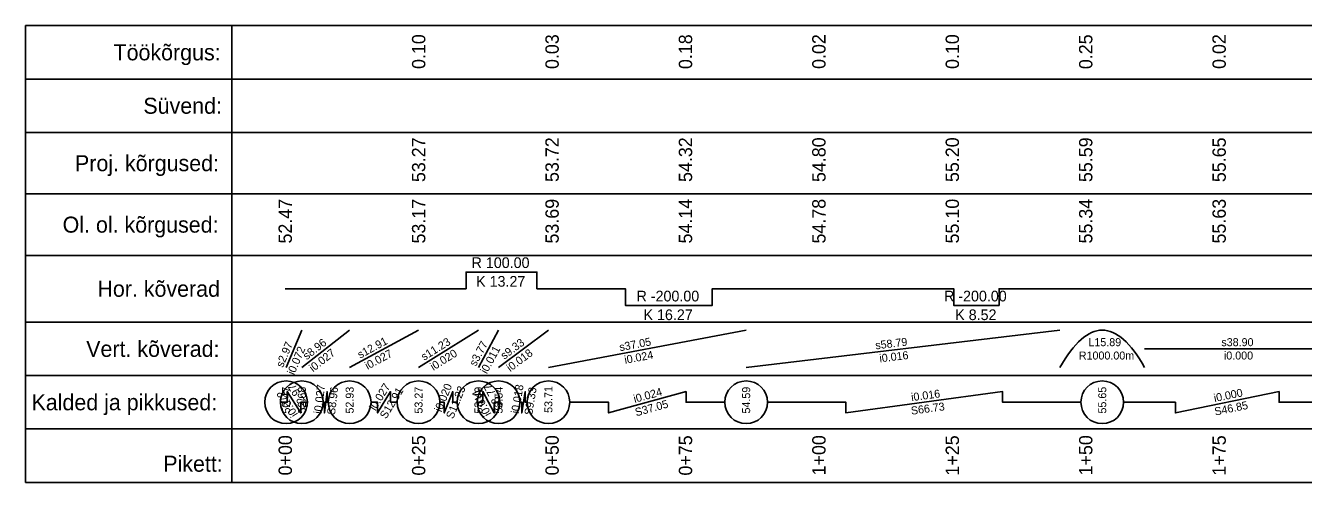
# Model space of a CAD drawing. Extents: x 655100 to 703495, y 6445581 to 6476602.
# Drawn here: x 669260.6 to 669500.1, y 6465749.1 to 6465834.6 of the extents above; entities that cross this region are included whole.
import ezdxf

# ---------------------------------------------------------------- set-up
doc = ezdxf.new("R2010")
doc.units = 0
for name, color, linetype in [('54', 7, 'Continuous'), ('Profile Annotation', 7, 'Continuous'), ('Prop_Benching', 7, 'Continuous')]:
    doc.layers.add(name, color=color, linetype=linetype)

msp = doc.modelspace()

# ---------------------------------------------------------------- linework, layer by layer
at = {"layer": '54'}
for points in [[(669299.3, 6465834.57), (669260.64, 6465834.57), (669260.64, 6465824.57), (669299.3, 6465824.57)], [(669309.3, 6465834.57), (669309.3, 6465834.57)], [(669334.3, 6465834.57), (669334.3, 6465834.57)], [(669359.3, 6465834.57), (669359.3, 6465834.57)], [(669384.3, 6465834.57), (669384.3, 6465834.57)], [(669409.3, 6465834.57), (669409.3, 6465834.57)], [(669434.3, 6465834.57), (669434.3, 6465834.57)], [(669459.3, 6465834.57), (669459.3, 6465834.57)], [(669484.3, 6465834.57), (669484.3, 6465834.57)], [(669299.3, 6465824.57), (669260.64, 6465824.57), (669260.64, 6465814.57), (669299.3, 6465814.57)], [(669309.3, 6465824.57), (669309.3, 6465824.57)], [(669334.3, 6465824.57), (669334.3, 6465824.57)], [(669359.3, 6465824.57), (669359.3, 6465824.57)], [(669384.3, 6465824.57), (669384.3, 6465824.57)], [(669409.3, 6465824.57), (669409.3, 6465824.57)], [(669434.3, 6465824.57), (669434.3, 6465824.57)], [(669459.3, 6465824.57), (669459.3, 6465824.57)], [(669484.3, 6465824.57), (669484.3, 6465824.57)], [(669299.3, 6465814.57), (669260.64, 6465814.57), (669260.64, 6465803.07), (669299.3, 6465803.07)], [(669309.3, 6465814.57), (669309.3, 6465814.57)], [(669334.3, 6465814.57), (669334.3, 6465814.57)], [(669359.3, 6465814.57), (669359.3, 6465814.57)], [(669384.3, 6465814.57), (669384.3, 6465814.57)], [(669409.3, 6465814.57), (669409.3, 6465814.57)], [(669434.3, 6465814.57), (669434.3, 6465814.57)], [(669459.3, 6465814.57), (669459.3, 6465814.57)], [(669484.3, 6465814.57), (669484.3, 6465814.57)], [(669299.3, 6465803.07), (669260.64, 6465803.07), (669260.64, 6465791.57), (669299.3, 6465791.57)], [(669309.3, 6465803.07), (669309.3, 6465803.07)], [(669334.3, 6465803.07), (669334.3, 6465803.07)], [(669359.3, 6465803.07), (669359.3, 6465803.07)], [(669384.3, 6465803.07), (669384.3, 6465803.07)], [(669409.3, 6465803.07), (669409.3, 6465803.07)], [(669434.3, 6465803.07), (669434.3, 6465803.07)], [(669459.3, 6465803.07), (669459.3, 6465803.07)], [(669484.3, 6465803.07), (669484.3, 6465803.07)], [(669299.3, 6465791.57), (669260.64, 6465791.57), (669260.64, 6465779.07), (669299.3, 6465779.07)], [(669309.3, 6465791.57), (669309.3, 6465791.57)], [(669343.19, 6465791.57), (669343.19, 6465791.57)], [(669356.46, 6465791.57), (669356.46, 6465791.57)], [(669373.06, 6465791.57), (669373.06, 6465791.57)], [(669389.33, 6465791.57), (669389.33, 6465791.57)], [(669434.56, 6465791.57), (669434.56, 6465791.57)], [(669443.08, 6465791.57), (669443.08, 6465791.57)], [(669299.3, 6465779.07), (669260.64, 6465779.07), (669260.64, 6465769.07), (669299.3, 6465769.07)], [(669309.45, 6465779.07), (669309.45, 6465779.07)], [(669312.41, 6465779.07), (669312.41, 6465779.07)], [(669321.37, 6465779.07), (669321.37, 6465779.07)], [(669334.28, 6465779.07), (669334.28, 6465779.07)], [(669345.51, 6465779.07), (669345.51, 6465779.07)], [(669349.28, 6465779.07), (669349.28, 6465779.07)], [(669358.61, 6465779.07), (669358.61, 6465779.07)], [(669395.67, 6465779.07), (669395.67, 6465779.07)], [(669454.46, 6465779.07), (669454.46, 6465779.07)], [(669470.34, 6465779.07), (669470.34, 6465779.07)], [(669299.3, 6465769.07), (669260.64, 6465769.07), (669260.64, 6465759.07), (669299.3, 6465759.07)], [(669309.45, 6465769.07), (669309.45, 6465769.07)], [(669312.41, 6465769.07), (669312.41, 6465769.07)], [(669321.37, 6465769.07), (669321.37, 6465769.07)], [(669334.28, 6465769.07), (669334.28, 6465769.07)], [(669345.51, 6465769.07), (669345.51, 6465769.07)], [(669349.28, 6465769.07), (669349.28, 6465769.07)], [(669358.61, 6465769.07), (669358.61, 6465769.07)], [(669395.67, 6465769.07), (669395.67, 6465769.07)], [(669454.46, 6465769.07), (669454.46, 6465769.07)], [(669470.34, 6465769.07), (669470.34, 6465769.07)], [(669299.3, 6465759.07), (669260.64, 6465759.07), (669260.64, 6465749.07), (669299.3, 6465749.07)], [(669309.3, 6465759.07), (669309.3, 6465759.07)], [(669334.3, 6465759.07), (669334.3, 6465759.07)], [(669359.3, 6465759.07), (669359.3, 6465759.07)], [(669384.3, 6465759.07), (669384.3, 6465759.07)], [(669409.3, 6465759.07), (669409.3, 6465759.07)], [(669434.3, 6465759.07), (669434.3, 6465759.07)], [(669459.3, 6465759.07), (669459.3, 6465759.07)], [(669484.3, 6465759.07), (669484.3, 6465759.07)]]:
    msp.add_lwpolyline(points, dxfattribs=at)
for points in [[(669299.3, 6465824.57), (670219.3, 6465824.57), (670219.3, 6465834.57), (669299.3, 6465834.57)], [(669299.3, 6465814.57), (670219.3, 6465814.57), (670219.3, 6465824.57), (669299.3, 6465824.57)], [(669299.3, 6465803.07), (670219.3, 6465803.07), (670219.3, 6465814.57), (669299.3, 6465814.57)], [(669299.3, 6465791.57), (670219.3, 6465791.57), (670219.3, 6465803.07), (669299.3, 6465803.07)], [(669299.3, 6465779.07), (670219.3, 6465779.07), (670219.3, 6465791.57), (669299.3, 6465791.57)], [(669299.3, 6465769.07), (670219.3, 6465769.07), (670219.3, 6465779.07), (669299.3, 6465779.07)], [(669299.3, 6465759.07), (670219.3, 6465759.07), (670219.3, 6465769.07), (669299.3, 6465769.07)], [(669299.3, 6465749.07), (670219.3, 6465749.07), (670219.3, 6465759.07), (669299.3, 6465759.07)]]:
    msp.add_lwpolyline(points, close=True, dxfattribs=at)
at = {"layer": 'Profile Annotation'}
for points in [[(669309.3, 6465785.32), (669343.19, 6465785.32), (669343.19, 6465788.45), (669356.46, 6465788.45), (669356.46, 6465785.32), (669373.06, 6465785.32), (669373.06, 6465782.2), (669389.33, 6465782.2), (669389.33, 6465785.32), (669434.56, 6465785.32), (669434.56, 6465782.2), (669443.08, 6465782.2), (669443.08, 6465785.32), (669626.89, 6465785.32), (669626.89, 6465788.45), (669648.62, 6465788.45), (669648.62, 6465785.32), (669796.34, 6465785.32)], [(669309.45, 6465770.57), (669312.41, 6465777.57)], [(669312.41, 6465770.57), (669321.37, 6465777.57)], [(669321.37, 6465770.57), (669334.28, 6465777.57)], [(669334.28, 6465770.57), (669345.51, 6465777.57)], [(669345.51, 6465770.57), (669349.28, 6465777.57)], [(669349.28, 6465770.57), (669358.61, 6465777.57)], [(669358.61, 6465770.57), (669395.67, 6465777.57)], [(669395.67, 6465770.57), (669454.46, 6465777.57)], [(669454.46, 6465770.57), (669454.95, 6465771.42), (669455.45, 6465772.21), (669455.94, 6465772.95), (669456.44, 6465773.64), (669456.94, 6465774.26), (669457.43, 6465774.84), (669457.93, 6465775.36), (669458.43, 6465775.82), (669458.92, 6465776.23), (669459.42, 6465776.59), (669459.92, 6465776.89), (669460.41, 6465777.14), (669460.91, 6465777.33), (669461.41, 6465777.46), (669461.9, 6465777.55), (669462.9, 6465777.55), (669463.39, 6465777.46), (669463.89, 6465777.33), (669464.39, 6465777.14), (669464.88, 6465776.89), (669465.38, 6465776.59), (669465.88, 6465776.23), (669466.37, 6465775.82), (669466.87, 6465775.36), (669467.37, 6465774.84), (669467.86, 6465774.26), (669468.36, 6465773.64), (669468.85, 6465772.95), (669469.35, 6465772.21), (669469.85, 6465771.42), (669470.34, 6465770.57)], [(669470.34, 6465774.07), (669509.25, 6465774.07)], [(669313.45, 6465764.07), (669312.19, 6465764.07), (669312.19, 6465762.07), (669309.67, 6465766.07), (669309.67, 6465764.07), (669308.41, 6465764.07)], [(669316.41, 6465764.07), (669316.65, 6465764.07), (669316.65, 6465762.07), (669317.13, 6465766.07), (669317.13, 6465764.07), (669317.37, 6465764.07)], [(669325.37, 6465764.07), (669326.6, 6465764.07), (669326.6, 6465762.07), (669329.05, 6465766.07), (669329.05, 6465764.07), (669330.28, 6465764.07)], [(669338.28, 6465764.07), (669339.09, 6465764.07), (669339.09, 6465762.07), (669340.7, 6465766.07), (669340.7, 6465764.07), (669341.51, 6465764.07)], [(669349.51, 6465764.07), (669348.45, 6465764.07), (669348.45, 6465762.07), (669346.34, 6465766.07), (669346.34, 6465764.07), (669345.28, 6465764.07)], [(669353.28, 6465764.07), (669353.61, 6465764.07), (669353.61, 6465762.07), (669354.28, 6465766.07), (669354.28, 6465764.07), (669354.61, 6465764.07)], [(669362.61, 6465764.07), (669369.88, 6465764.07), (669369.88, 6465762.07), (669384.41, 6465766.07), (669384.41, 6465764.07), (669391.67, 6465764.07)], [(669399.67, 6465764.07), (669414.35, 6465764.07), (669414.35, 6465762.07), (669443.72, 6465766.07), (669443.72, 6465764.07), (669458.4, 6465764.07)], [(669466.4, 6465764.07), (669476.11, 6465764.07), (669476.11, 6465762.07), (669495.54, 6465766.07), (669495.54, 6465764.07), (669505.25, 6465764.07)]]:
    msp.add_lwpolyline(points, dxfattribs=at)
for centre in [(669309.45, 6465764.07), (669312.41, 6465764.07), (669321.37, 6465764.07), (669334.28, 6465764.07), (669345.51, 6465764.07), (669349.28, 6465764.07), (669358.61, 6465764.07), (669395.67, 6465764.07), (669462.4, 6465764.07)]:
    msp.add_circle(centre, 4, dxfattribs=at)

# ---------------------------------------------------------------- texts
for s, height, rotation, p in [('0.10', 2.5, 90, (669335.55, 6465826.45)), ('0.03', 2.5, 90, (669360.55, 6465826.44)), ('0.18', 2.5, 90, (669385.55, 6465826.43)), ('0.02', 2.5, 90, (669410.55, 6465826.46)), ('0.10', 2.5, 90, (669435.55, 6465826.45)), ('0.25', 2.5, 90, (669460.55, 6465826.42)), ('0.02', 2.5, 90, (669485.55, 6465826.46)), ('53.27', 2.5, 90, (669335.55, 6465805.28)), ('53.72', 2.5, 90, (669360.55, 6465805.3)), ('54.32', 2.5, 90, (669385.55, 6465805.3)), ('54.80', 2.5, 90, (669410.55, 6465805.29)), ('55.20', 2.5, 90, (669435.55, 6465805.29)), ('55.59', 2.5, 90, (669460.55, 6465805.28)), ('55.65', 2.5, 90, (669485.55, 6465805.27)), ('52.47', 2.5, 90, (669310.55, 6465793.78)), ('53.17', 2.5, 90, (669335.55, 6465793.78)), ('53.69', 2.5, 90, (669360.55, 6465793.78)), ('54.14', 2.5, 90, (669385.55, 6465793.79)), ('54.78', 2.5, 90, (669410.55, 6465793.78)), ('55.10', 2.5, 90, (669435.55, 6465793.79)), ('55.34', 2.5, 90, (669460.55, 6465793.79)), ('55.63', 2.5, 90, (669485.55, 6465793.78)), ('s2.97', 1.5, 67.0425, (669308.86, 6465770.47)), ('s8.96', 1.5, 37.9971, (669313.33, 6465771.93)), ('s12.91', 1.5, 28.4648, (669323.33, 6465772.2)), ('s11.23', 1.5, 31.9471, (669335.32, 6465771.81)), ('s3.77', 1.5, 61.6763, (669345, 6465770.68)), ('s9.33', 1.5, 36.867, (669350.35, 6465772)), ('s37.05', 1.5, 10.6977, (669372.05, 6465773.62)), ('s58.79', 1.5, 6.7906, (669419.96, 6465773.97)), ('s38.90', 1.5, 360, (669484.72, 6465774.57)), ('i0.072', 1.5, 67.0425, (669310.98, 6465769.07)), ('i0.027', 1.5, 37.9971, (669314.5, 6465769.67)), ('i0.027', 1.5, 28.4648, (669324.74, 6465770.12)), ('i0.020', 1.5, 31.9471, (669337.05, 6465769.94)), ('i0.011', 1.5, 61.6763, (669347.08, 6465769.28)), ('i0.018', 1.5, 36.867, (669351.46, 6465769.71)), ('i0.024', 1.5, 10.6977, (669373, 6465771.25)), ('i0.016', 1.5, 6.7906, (669420.73, 6465771.54)), ('i0.000', 1.5, 360, (669485.2, 6465772.07)), ('i0.072', 1.5, 122.1843, (669311.73, 6465761.86)), ('52.47', 1.5, 90, (669310.2, 6465761.96)), ('S2.97', 1.5, 122.1843, (669313.79, 6465763.27)), ('52.68', 1.5, 90, (669313.16, 6465761.96)), ('i0.027', 1.5, 83.1535, (669316.12, 6465761.85)), ('S8.96', 1.5, 83.1535, (669318.61, 6465761.65)), ('52.93', 1.5, 90, (669322.12, 6465761.96)), ('i0.027', 1.5, 58.4537, (669326.2, 6465762.37)), ('S12.91', 1.5, 58.4537, (669328.19, 6465760.84)), ('53.27', 1.5, 90, (669335.03, 6465761.96)), ('i0.020', 1.5, 68.0421, (669338.57, 6465762.13)), ('S11.23', 1.5, 68.0421, (669340.75, 6465760.84)), ('i0.011', 1.5, 117.8517, (669347.97, 6465761.91)), ('53.49', 1.5, 90, (669346.26, 6465761.96)), ('S3.77', 1.5, 117.8517, (669350.19, 6465763.06)), ('53.54', 1.5, 90, (669350.03, 6465761.96)), ('i0.018', 1.5, 80.5309, (669353.08, 6465761.88)), ('S9.33', 1.5, 80.5309, (669355.56, 6465761.57)), ('53.71', 1.5, 90, (669359.36, 6465762.08)), ('i0.024', 1.5, 15.3945, (669374.79, 6465763.94)), ('54.59', 1.5, 90, (669396.42, 6465761.96)), ('i0.016', 1.5, 7.7569, (669426.69, 6465764.26)), ('55.65', 1.5, 90, (669463.15, 6465761.96)), ('i0.000', 1.5, 11.6361, (669483.47, 6465764.1)), ('S37.05', 1.5, 15.3945, (669375.08, 6465761.43)), ('S66.73', 1.5, 7.7569, (669426.65, 6465761.73)), ('S46.85', 1.5, 11.6361, (669483.59, 6465761.57)), ('0+00', 2.5, 90, (669310.55, 6465750.38)), ('0+25', 2.5, 90, (669335.55, 6465750.35)), ('0+50', 2.5, 90, (669360.55, 6465750.38)), ('0+75', 2.5, 90, (669385.55, 6465750.35)), ('1+00', 2.5, 90, (669410.55, 6465750.38)), ('1+25', 2.5, 90, (669435.55, 6465750.35)), ('1+50', 2.5, 90, (669460.55, 6465750.38)), ('1+75', 2.5, 90, (669485.55, 6465750.35))]:
    msp.add_text(s, height=height, rotation=rotation, dxfattribs=at).set_placement(p)
for s, height, p in [(' Töökõrgus: ', 3, (669276.01, 6465828.07)), (' Süvend: ', 3, (669281.6, 6465818.07)), (' Proj. kõrgused: ', 3, (669268.79, 6465807.32)), (' Ol. ol. kõrgused: ', 3, (669266.47, 6465795.82)), (' Hor. kõverad ', 3, (669272.99, 6465783.82)), (' Vert. kõverad: ', 3, (669270.89, 6465772.57)), ('L15.89', 1.5, (669459.81, 6465774.57)), ('R1000.00m', 1.5, (669458.01, 6465772.07)), (' Kalded ja pikkused: ', 3, (669260.64, 6465762.57)), (' Pikett: ', 3, (669285.33, 6465751.07))]:
    msp.add_text(s, height=height, dxfattribs=at).set_placement(p)
at = {"layer": 'Prop_Benching'}
for s, p in [('R 100.00', (669344.22, 6465789.2)), ('K 13.27', (669345.07, 6465785.7)), ('R -200.00', (669375.13, 6465782.95)), ('R -200.00', (669432.75, 6465782.95)), ('K 16.27', (669376.44, 6465779.45)), ('K 8.52', (669434.85, 6465779.45))]:
    msp.add_text(s, height=2, dxfattribs=at).set_placement(p)

doc.saveas('drawing.dxf')
